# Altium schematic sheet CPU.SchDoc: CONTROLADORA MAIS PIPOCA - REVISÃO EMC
size A3; DocumentNumber: GA0050; SheetNumber: 3; SheetTotal: 17
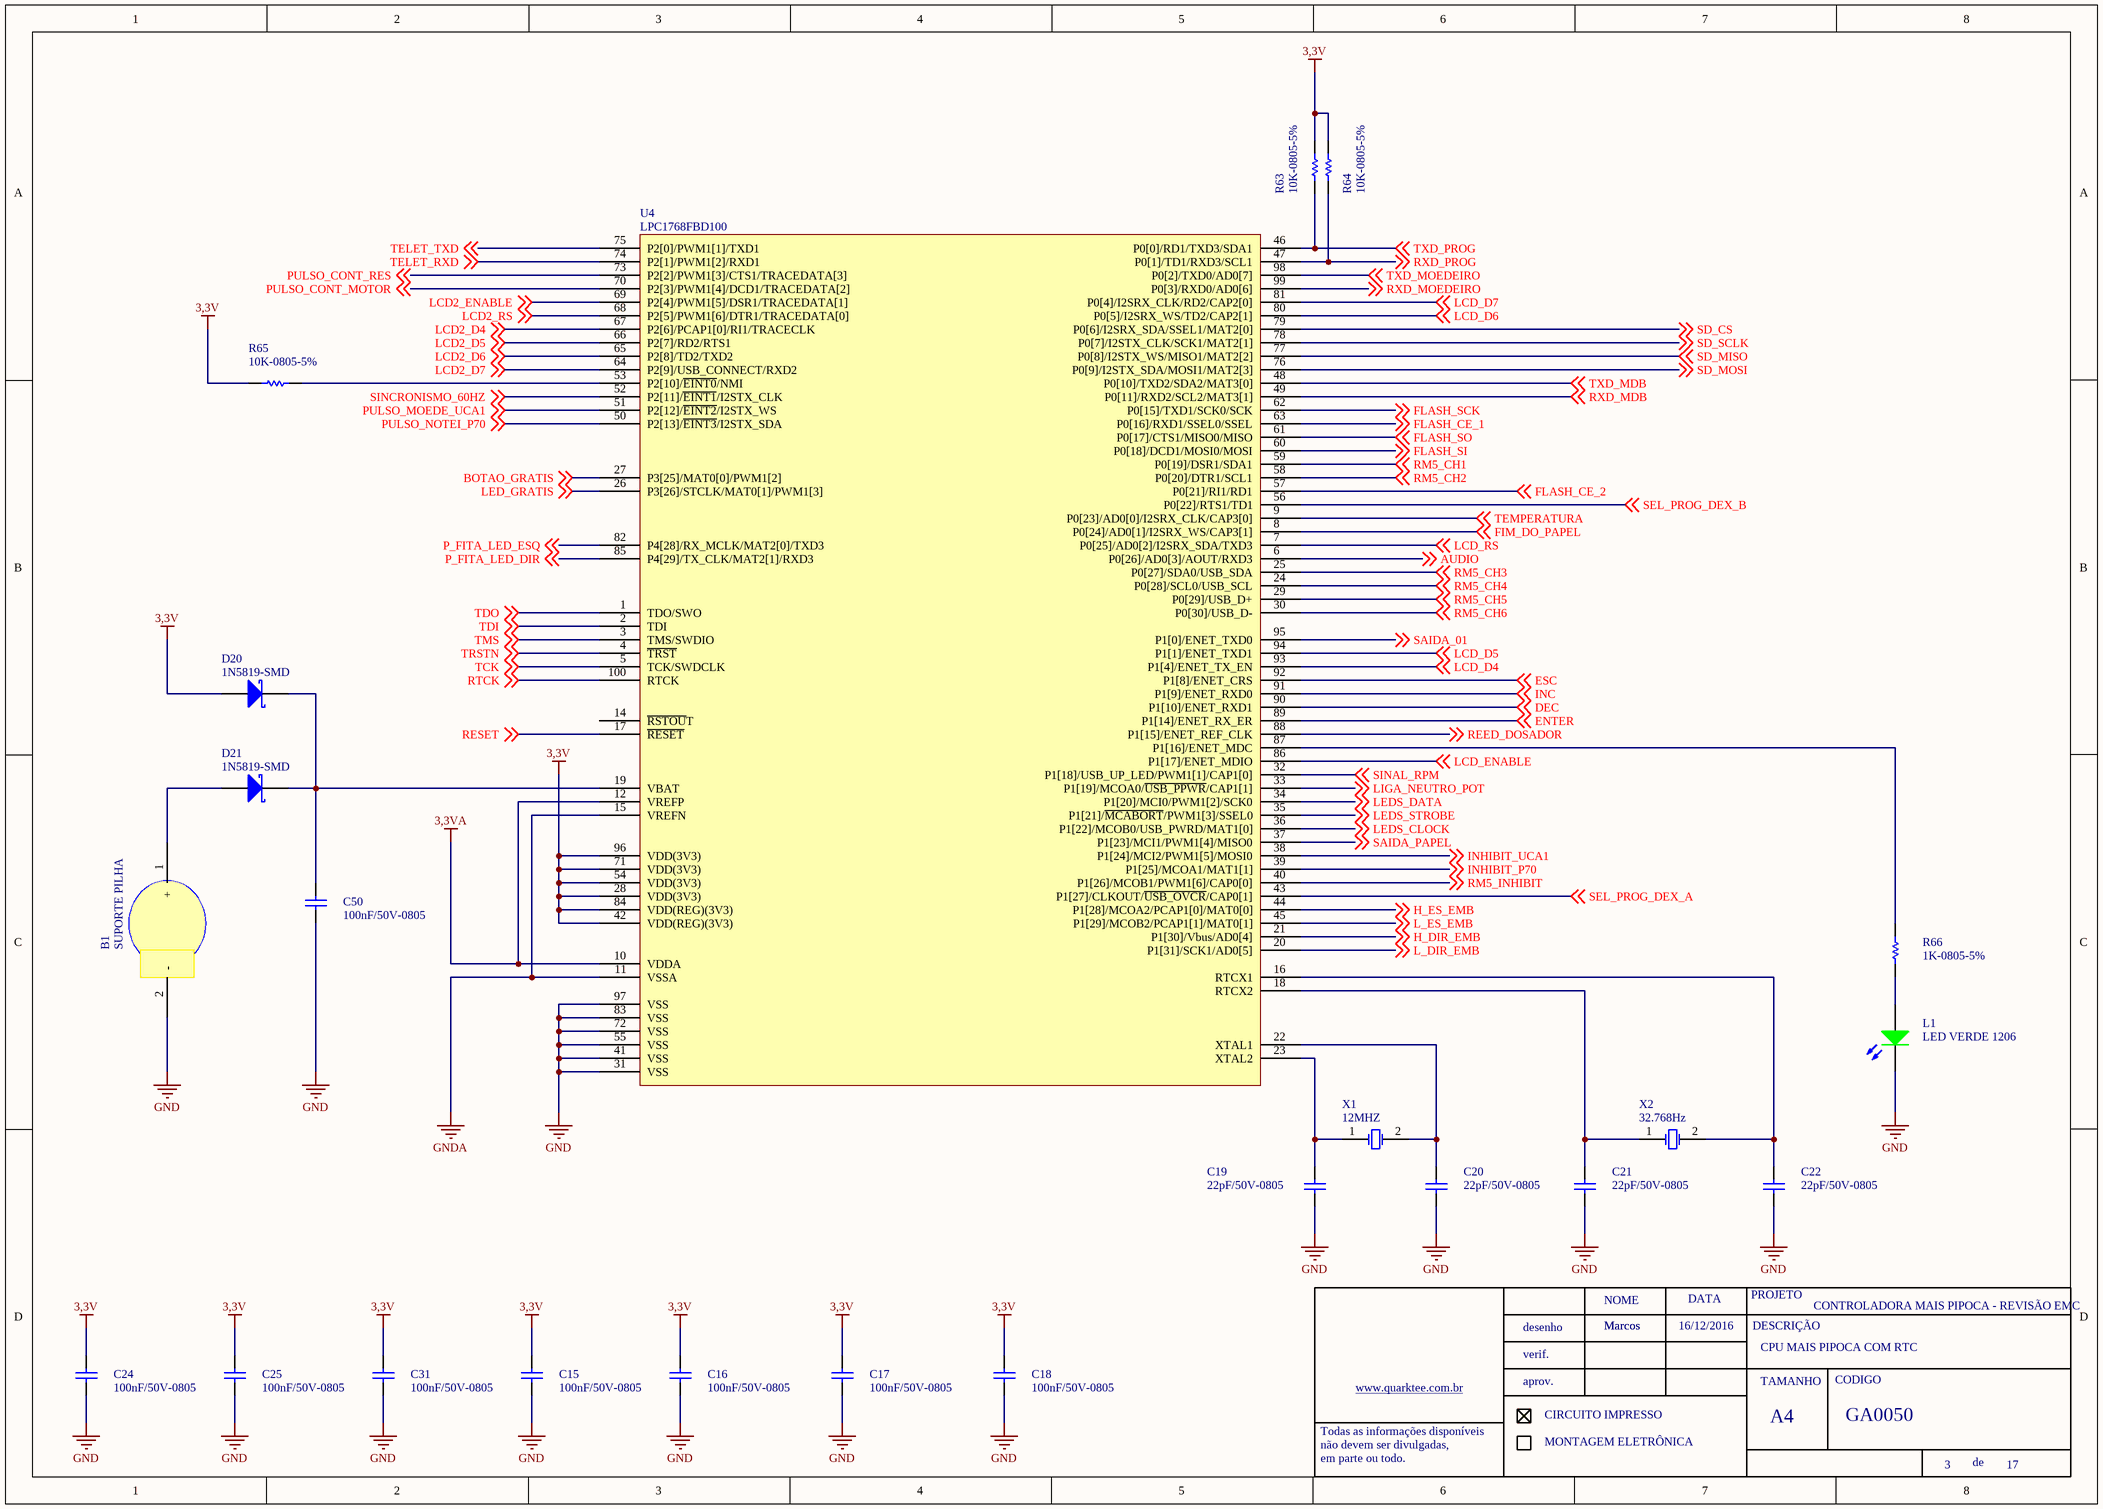
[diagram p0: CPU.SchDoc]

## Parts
B1  SUPORTE PILHA  [SUPORTE PILHA CR2032]
C15  100nF/50V-0805  [0805-REVISADO ONDA]
C16  100nF/50V-0805  [0805-REVISADO ONDA]
C17  100nF/50V-0805  [0805-REVISADO ONDA]
C18  100nF/50V-0805  [0805-REVISADO ONDA]
C19  22pF/50V-0805  [0805-REVISADO ONDA]
C20  22pF/50V-0805  [0805-REVISADO ONDA]
C21  22pF/50V-0805  [0805-REVISADO ONDA]
C22  22pF/50V-0805  [0805-REVISADO ONDA]
C24  100nF/50V-0805  [0805-REVISADO ONDA]
C25  100nF/50V-0805  [0805-REVISADO ONDA]
C31  100nF/50V-0805  [0805-REVISADO ONDA]
C50  100nF/50V-0805  [0805-REVISADO ONDA]
D20  1N5819-SMD
D21  1N5819-SMD
L1  LED VERDE 1206  [LED 1206]
R63  10K-0805-5%  [0805-REVISADO ONDA]
R64  10K-0805-5%  [0805-REVISADO ONDA]
R65  10K-0805-5%  [0805-REVISADO ONDA]
R66  1K-0805-5%  [0805-REVISADO ONDA]
U4  LPC1768FBD100  [LQFP-100 pasta]
X1  12MHZ  [HC49USM]
X2  32.768Hz  [CRISTAL TH3]

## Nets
3,3V: C15.2 C16.2 C17.2 C18.2 C24.2 C25.2 C31.2 D20.1(A) R63.2 R64.2 R65.1 U4.28(VDD(3V3)) U4.42(VDD(REG)(3V3)) U4.54(VDD(3V3)) U4.71(VDD(3V3)) U4.84(VDD(REG)(3V3)) U4.96(VDD(3V3))
3,3VA: U4.10(VDDA) U4.12(VREFP)
GND: B1.2(-) C15.1 C16.1 C17.1 C18.1 C19.1 C20.1 C21.1 C22.1 C24.1 C25.1 C31.1 C50.1 L1.2(K) U4.31(VSS) U4.41(VSS) U4.55(VSS) U4.72(VSS) U4.83(VSS) U4.97(VSS)
GNDA: U4.11(VSSA) U4.15(VREFN)
AUDIO: U4.6(P0[26]/AD0[3]/AOUT/RXD3) ; off-sheet AUDIO
BOTAO_GRATIS: U4.27(P3[25]/MAT0[0]/PWM1[2]) ; off-sheet BOTAO_GRATIS
DEC: U4.90(P1[10]/ENET_RXD1) ; off-sheet DEC
ENTER: U4.89(P1[14]/ENET_RX_ER) ; off-sheet ENTER
ESC: U4.92(P1[8]/ENET_CRS) ; off-sheet ESC
FIM_DO_PAPEL: U4.8(P0[24]/AD0[1]/I2SRX_WS/CAP3[1]) ; off-sheet FIM_DO_PAPEL
FLASH_CE_1: U4.63(P0[16]/RXD1/SSEL0/SSEL) ; off-sheet FLASH_CE_1
FLASH_CE_2: U4.57(P0[21]/RI1/RD1) ; off-sheet FLASH_CE_2
FLASH_SCK: U4.62(P0[15]/TXD1/SCK0/SCK) ; off-sheet FLASH_SCK
FLASH_SI: U4.60(P0[18]/DCD1/MOSI0/MOSI) ; off-sheet FLASH_SI
FLASH_SO: U4.61(P0[17]/CTS1/MISO0/MISO) ; off-sheet FLASH_SO
H_DIR_EMB: U4.21(P1[30]/Vbus/AD0[4]) ; off-sheet H_DIR_EMB
H_ES_EMB: U4.44(P1[28]/MCOA2/PCAP1[0]/MAT0[0]) ; off-sheet H_ES_EMB
INC: U4.91(P1[9]/ENET_RXD0) ; off-sheet INC
INHIBIT_P70: U4.39(P1[25]/MCOA1/MAT1[1]) ; off-sheet INHIBIT_P70
INHIBIT_UCA1: U4.38(P1[24]/MCI2/PWM1[5]/MOSI0) ; off-sheet INHIBIT_UCA1
L_DIR_EMB: U4.20(P1[31]/SCK1/AD0[5]) ; off-sheet L_DIR_EMB
L_ES_EMB: U4.45(P1[29]/MCOB2/PCAP1[1]/MAT0[1]) ; off-sheet L_ES_EMB
LCD2_D4: U4.67(P2[6]/PCAP1[0]/RI1/TRACECLK) ; off-sheet LCD2_D4
LCD2_D5: U4.66(P2[7]/RD2/RTS1) ; off-sheet LCD2_D5
LCD2_D6: U4.65(P2[8]/TD2/TXD2) ; off-sheet LCD2_D6
LCD2_D7: U4.64(P2[9]/USB_CONNECT/RXD2) ; off-sheet LCD2_D7
LCD2_ENABLE: U4.69(P2[4]/PWM1[5]/DSR1/TRACEDATA[1]) ; off-sheet LCD2_ENABLE
LCD2_RS: U4.68(P2[5]/PWM1[6]/DTR1/TRACEDATA[0]) ; off-sheet LCD2_RS
LCD_D4: U4.93(P1[4]/ENET_TX_EN) ; off-sheet LCD_D4
LCD_D5: U4.94(P1[1]/ENET_TXD1) ; off-sheet LCD_D5
LCD_D6: U4.80(P0[5]/I2SRX_WS/TD2/CAP2[1]) ; off-sheet LCD_D6
LCD_D7: U4.81(P0[4]/I2SRX_CLK/RD2/CAP2[0]) ; off-sheet LCD_D7
LCD_ENABLE: U4.86(P1[17]/ENET_MDIO) ; off-sheet LCD_ENABLE
LCD_RS: U4.7(P0[25]/AD0[2]/I2SRX_SDA/TXD3) ; off-sheet LCD_RS
LED_GRATIS: U4.26(P3[26]/STCLK/MAT0[1]/PWM1[3]) ; off-sheet LED_GRATIS
LEDS_CLOCK: U4.36(P1[22]/MCOB0/USB_PWRD/MAT1[0]) ; off-sheet LEDS_CLOCK
LEDS_DATA: U4.34(P1[20]/MCI0/PWM1[2]/SCK0) ; off-sheet LEDS_DATA
LEDS_STROBE: U4.35(P1[21]/~{MCABORT}/PWM1[3]/SSEL0) ; off-sheet LEDS_STROBE
LIGA_NEUTRO_POT: U4.33(P1[19]/MCOA0/~{USB_PPWR}/CAP1[1]) ; off-sheet LIGA_NEUTRO_POT
P_FITA_LED_DIR: U4.85(P4[29]/TX_CLK/MAT2[1]/RXD3) ; off-sheet P_FITA_LED_DIR
P_FITA_LED_ESQ: U4.82(P4[28]/RX_MCLK/MAT2[0]/TXD3) ; off-sheet P_FITA_LED_ESQ
PULSO_CONT_MOTOR: U4.70(P2[3]/PWM1[4]/DCD1/TRACEDATA[2]) ; off-sheet PULSO_CONT_MOTOR
PULSO_CONT_RES: U4.73(P2[2]/PWM1[3]/CTS1/TRACEDATA[3]) ; off-sheet PULSO_CONT_RES
PULSO_MOEDE_UCA1: U4.51(P2[12]/~{EINT2}/I2STX_WS) ; off-sheet PULSO_MOEDE_UCA1
PULSO_NOTEI_P70: U4.50(P2[13]/~{EINT3}/I2STX_SDA) ; off-sheet PULSO_NOTEI_P70
REED_DOSADOR: U4.88(P1[15]/ENET_REF_CLK) ; off-sheet REED_DOSADOR
RESET: U4.17(~{RESET}) ; off-sheet RESET
RM5_CH1: U4.59(P0[19]/DSR1/SDA1) ; off-sheet RM5_CH1
RM5_CH2: U4.58(P0[20]/DTR1/SCL1) ; off-sheet RM5_CH2
RM5_CH3: U4.25(P0[27]/SDA0/USB_SDA) ; off-sheet RM5_CH3
RM5_CH4: U4.24(P0[28]/SCL0/USB_SCL) ; off-sheet RM5_CH4
RM5_CH5: U4.29(P0[29]/USB_D+) ; off-sheet RM5_CH5
RM5_CH6: U4.30(P0[30]/USB_D-) ; off-sheet RM5_CH6
RM5_INHIBIT: U4.40(P1[26]/MCOB1/PWM1[6]/CAP0[0]) ; off-sheet RM5_INHIBIT
RTCK: U4.100(RTCK) ; off-sheet RTCK
RXD_MDB: U4.49(P0[11]/RXD2/SCL2/MAT3[1]) ; off-sheet RXD_MDB
RXD_MOEDEIRO: U4.99(P0[3]/RXD0/AD0[6]) ; off-sheet RXD_MOEDEIRO
RXD_PROG: R64.1 U4.47(P0[1]/TD1/RXD3/SCL1) ; off-sheet RXD_PROG
SAIDA_01: U4.95(P1[0]/ENET_TXD0) ; off-sheet SAIDA_01
SAIDA_PAPEL: U4.37(P1[23]/MCI1/PWM1[4]/MISO0) ; off-sheet SAIDA_PAPEL
SD_CS: U4.79(P0[6]/I2SRX_SDA/SSEL1/MAT2[0]) ; off-sheet SD_CS
SD_MISO: U4.77(P0[8]/I2STX_WS/MISO1/MAT2[2]) ; off-sheet SD_MISO
SD_MOSI: U4.76(P0[9]/I2STX_SDA/MOSI1/MAT2[3]) ; off-sheet SD_MOSI
SD_SCLK: U4.78(P0[7]/I2STX_CLK/SCK1/MAT2[1]) ; off-sheet SD_SCLK
SEL_PROG_DEX_A: U4.43(P1[27]/CLKOUT/~{USB_OVCR}/CAP0[1]) ; off-sheet SEL_PROG_DEX_A
SEL_PROG_DEX_B: U4.56(P0[22]/RTS1/TD1) ; off-sheet SEL_PROG_DEX_B
SINAL_RPM: U4.32(P1[18]/USB_UP_LED/PWM1[1]/CAP1[0]) ; off-sheet SINAL_RPM
SINCRONISMO_60HZ: U4.52(P2[11]/~{EINT1}/I2STX_CLK) ; off-sheet SINCRONISMO_60HZ
TCK: U4.5(TCK/SWDCLK) ; off-sheet TCK
TDI: U4.2(TDI) ; off-sheet TDI
TDO: U4.1(TDO/SWO) ; off-sheet TDO
TELET_RXD: U4.74(P2[1]/PWM1[2]/RXD1) ; off-sheet TELET_RXD
TELET_TXD: U4.75(P2[0]/PWM1[1]/TXD1) ; off-sheet TELET_TXD
TEMPERATURA: U4.9(P0[23]/AD0[0]/I2SRX_CLK/CAP3[0]) ; off-sheet TEMPERATURA
TMS: U4.3(TMS/SWDIO) ; off-sheet TMS
TRSTN: U4.4(~{TRST}) ; off-sheet TRSTN
TXD_MDB: U4.48(P0[10]/TXD2/SDA2/MAT3[0]) ; off-sheet TXD_MDB
TXD_MOEDEIRO: U4.98(P0[2]/TXD0/AD0[7]) ; off-sheet TXD_MOEDEIRO
TXD_PROG: R63.1 U4.46(P0[0]/RD1/TXD3/SDA1) ; off-sheet TXD_PROG
NetB1_1: B1.1(+) D21.1(A)
NetC19_2: C19.2 U4.23(XTAL2) X1.1(OSC1)
NetC20_2: C20.2 U4.22(XTAL1) X1.2(OSC2)
NetC21_2: C21.2 U4.18(RTCX2) X2.1(OSC1)
NetC22_2: C22.2 U4.16(RTCX1) X2.2(OSC2)
NetC50_2: C50.2 D20.2(K) D21.2(K) U4.19(VBAT)
NetL1_1: L1.1(A) R66.1
NetR65_2: R65.2 U4.53(P2[10]/~{EINT0}/NMI)
NetR66_2: R66.2 U4.87(P1[16]/ENET_MDC)

Not connected (* = marked no-connect by the designer): U4 14(~{RSTOU}T)

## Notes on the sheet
- Marcos
- 16/12/2016
- CPU MAIS PIPOCA COM RTC

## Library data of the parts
B1 = SUPORTE PILHA CR2032
C15-C18 C24 C25 C31 C50 = 100nF/50-0805-NPO
C19-C22 = 22pF-0805-NPO
D20 D21 = 1N5819
L1 = LED VERDE 0603 SMD: LED VERDE 0603 VERDE
U4 = LPC1768FDB100
X1 = CRISTAL 12MHZ
X2 = CRISTAL 32.768 Hz: CRISTAL 32.768Hz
